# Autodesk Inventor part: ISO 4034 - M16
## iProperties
Comments: To add or edit properties for Autodesk Inventor files, use iProperties.
Created: 2004-01
Part Number: ISO 4034 - M16
Vendor: Autodesk Inc.
Document SubType Name: Modeling
Designer: Administratör
Material: Standard
Description: Sexkantsmutter
Standard: ISO 4034
Alert: To add or edit properties for Autodesk Inventor files, use iProperties.
Control State: 0
Master: False
Checked Out: False
Shininess: 64.0
Length Units: 11269
Angle Units: 11279
Time Units: 11290
Mass Units: 11283
Length Display Precision: 3
Angle Display Precision: 2
Compacted: True
EGR: 1
Density: 0.0
Volumn: 0.0
Area: 0.0
PropertySet Name: Model Information
Author: Administratör
Revision Number: 8
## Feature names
1. Kropp [Extrusion]
2. Fas1 [Revolution]
3. Gänga [Hole]
4. Fas2 [Chamfer]
5. Fas3 [Chamfer]
